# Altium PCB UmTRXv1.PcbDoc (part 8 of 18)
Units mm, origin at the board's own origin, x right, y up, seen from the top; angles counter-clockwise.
Board outline 172 x 113 mm, 6 copper layers (Top Layer, GND, MidLayer1, Mid-Layer 2, InternalPlane2, Bottom Layer); 766 components, 613 nets, 3008 pads, 1360 vias.
Unrouted connection lines stored in the file: 2.
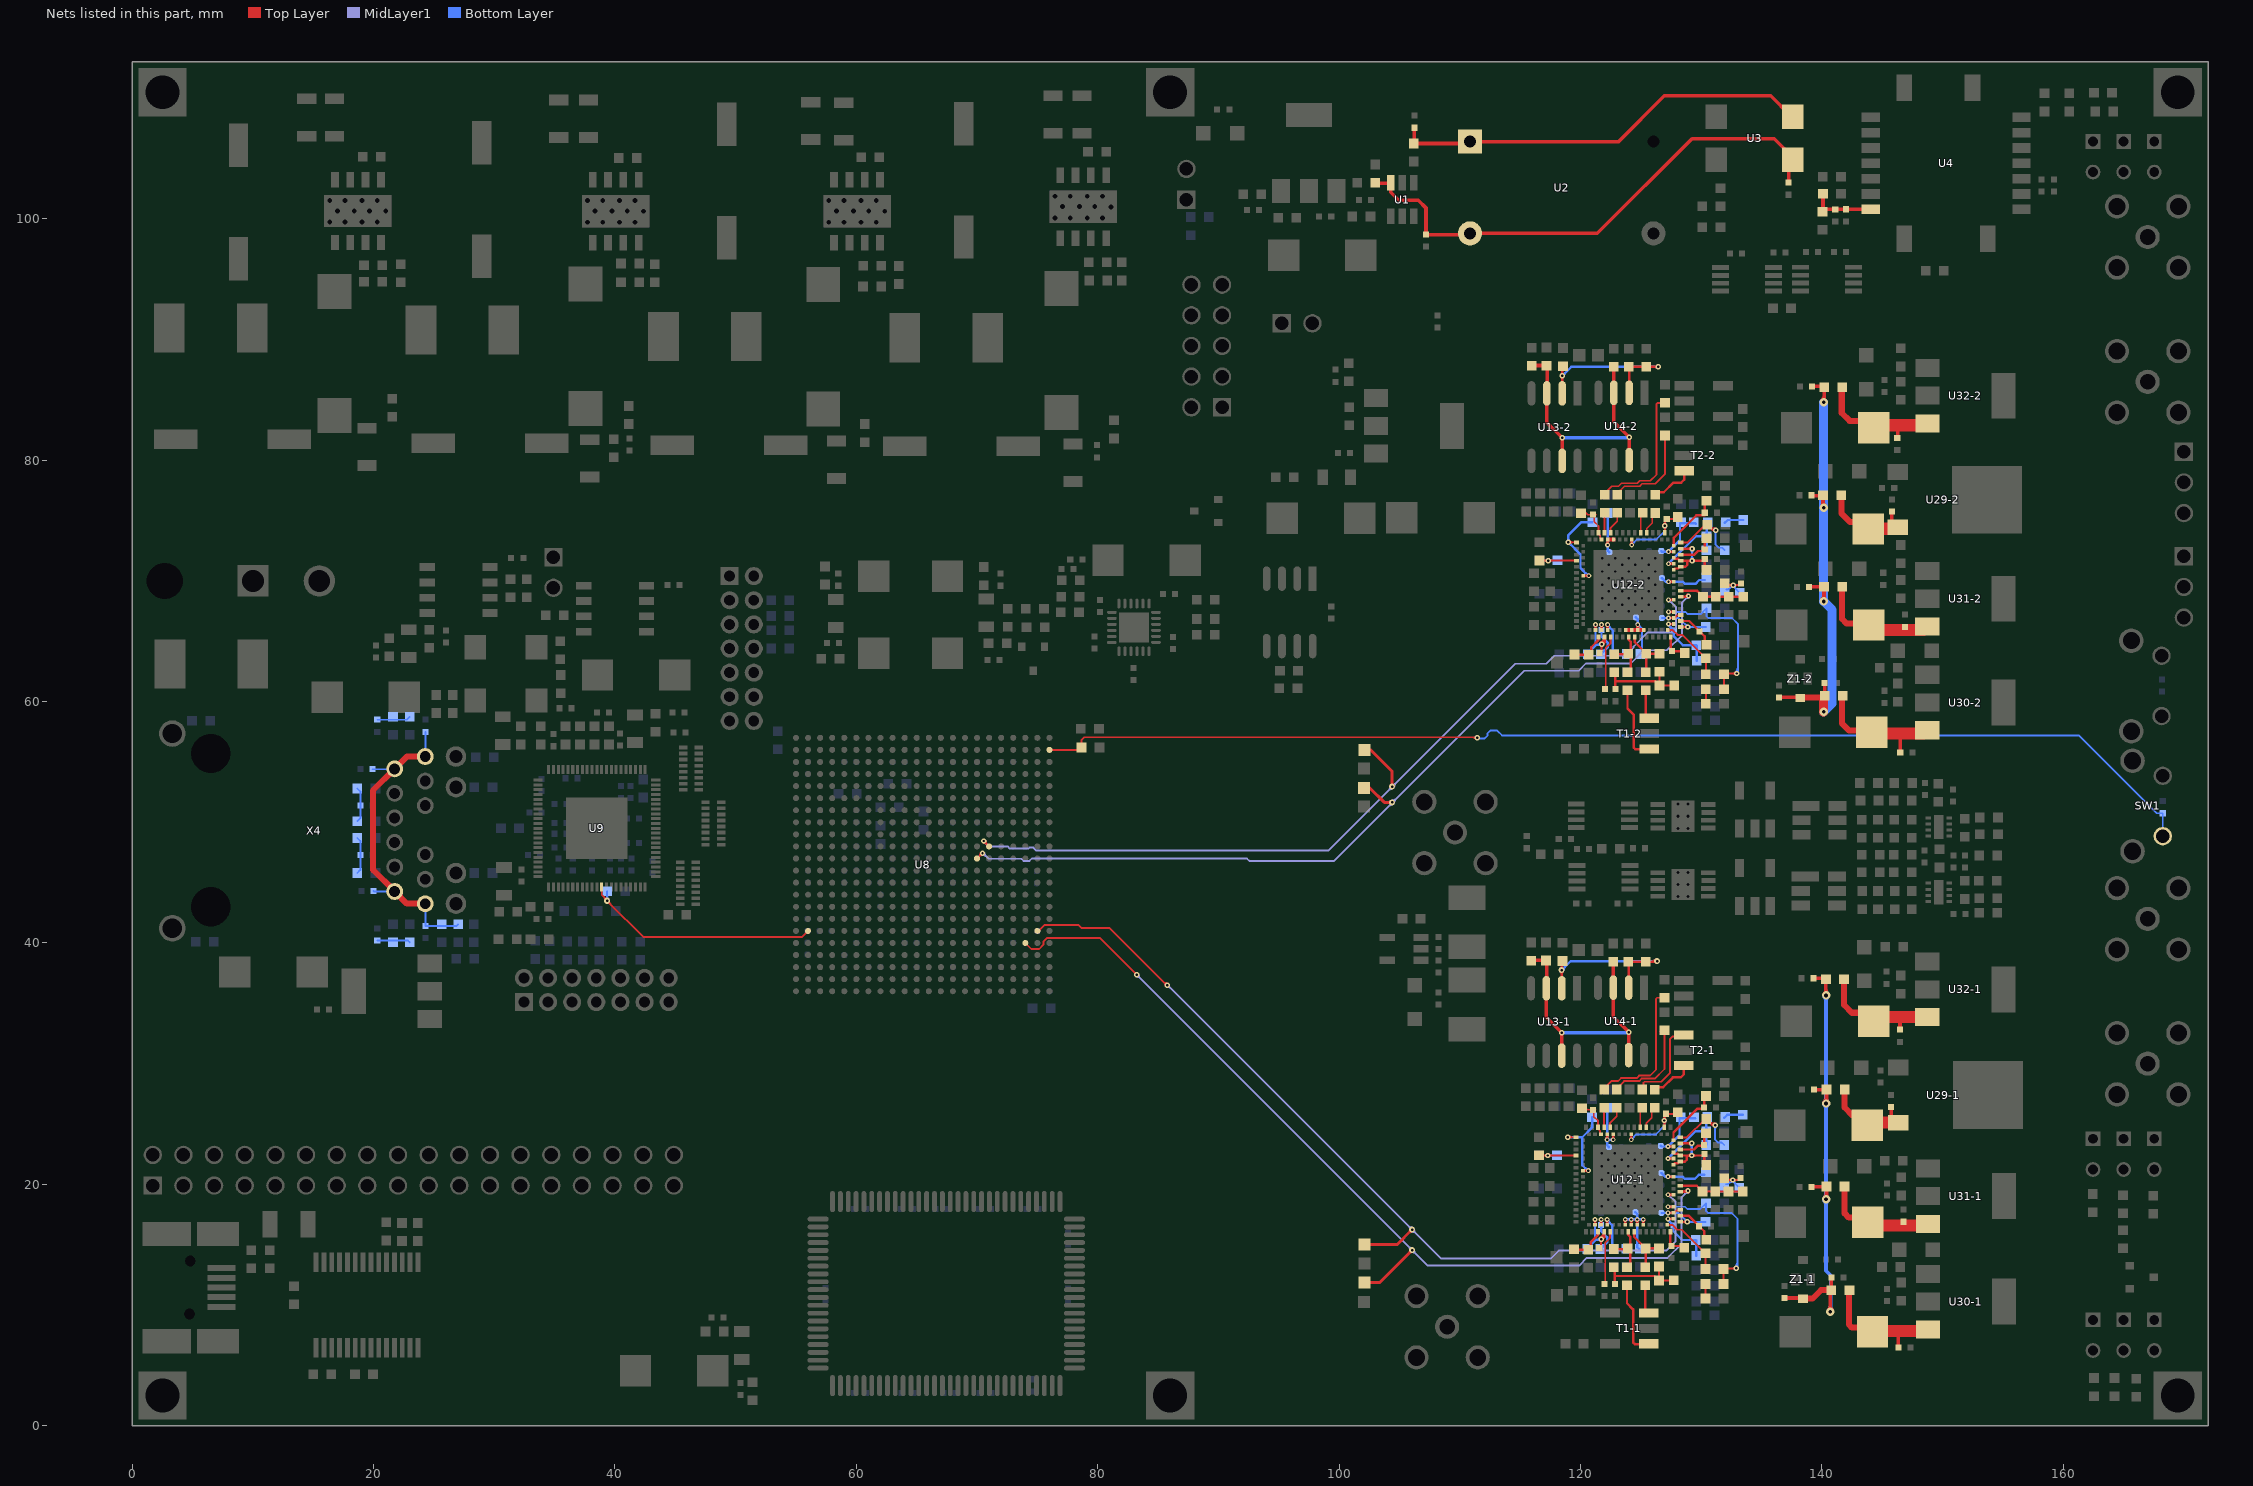
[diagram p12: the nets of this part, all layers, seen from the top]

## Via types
v1: diameter 0.45, hole 0.2, Top Layer to Bottom Layer, tented both sides, 554 vias
v2: diameter 0.5, hole 0.2, Top Layer to Bottom Layer, tented both sides, 468 vias
v3: diameter 0.7, hole 0.3, Top Layer to Bottom Layer, tented both sides, 206 vias
v4: diameter 0.4, hole 0.2, Top Layer to Bottom Layer, tented both sides, 82 vias
v5: diameter 0.8, hole 0.3, Top Layer to Bottom Layer, tented both sides, 16 vias
v6: diameter 0.6, hole 0.25, Top Layer to Bottom Layer, tented both sides, 16 vias
v7: diameter 0.5, hole 0.3, Top Layer to Bottom Layer, tented both sides, 8 vias
v8: diameter 0.7, hole 0.3, Top Layer to Bottom Layer, 4 vias
v9: diameter 0.6, hole 0.3, Top Layer to Bottom Layer, tented both sides, 4 vias
v10: diameter 0.5, hole 0.2, Top Layer to Bottom Layer, 2 vias

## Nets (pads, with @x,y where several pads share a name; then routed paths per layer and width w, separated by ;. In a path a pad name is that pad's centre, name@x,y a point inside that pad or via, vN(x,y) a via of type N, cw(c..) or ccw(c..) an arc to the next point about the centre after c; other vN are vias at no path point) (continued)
MDIO: R92.2 U8.F21 U9.54 | length 22.3
  Top Layer w0.15: U9.54@38.9,44.625 38.9,44 39.55,43.35 v2@39.5,43.35 ; 39.016,43.884 cw(c38.632,43.5) v2@39.175,43.5 ; 39.137,43.763 ccw(c39.35,43.977) v2@39.35,43.675 ; v2@39.35,43.325 cw(c39.35,42.903) 39.649,43.201 cw(c39.947,43.5) v2@39.525,43.5 ; v2@39.45,43.4 v2@39.5,43.35 ; U8.F21@56,41 55.5,40.5 42.35,40.5 v2@39.5,43.35
  Bottom Layer w0.15: v2@39.226,43.624 ccw(c38.928,43.922) 39.35,43.922 ccw(c39.772,43.922) v2@39.474,43.624 ; v2(39.35,43.5) R92.2@39.35,44.287
MISO1: U8.F2 U12-1.68 X21.1 | length 78
  Top Layer w0.15: U8.F2@75,41 75.1,41 75.6,41.5 78.4,41.5 78.65,41.25 80.966,41.25 85.75,36.466 v1@85.75,36.45 ; 85.435,36.78 ccw(c85.75,37.095) v1@85.75,36.65 ; 85.518,36.697 cw(c85.321,36.5) v1@85.6,36.5
  Top Layer w0.2: v4@127.282,19.138 U12-1.68@127.707,19.138 ; v4@127.328,19.067 cw(c127.498,18.897) 127.498,19.138 cw(c127.498,19.379) v4@127.328,19.209
  Top Layer w0.25: X21.1@102.1,15 104.8,15 v2(106.05,16.25) ; v2@105.925,16.25 cw(c105.623,16.25) 105.837,16.037 cw(c106.05,15.823) v2@106.05,16.125
  MidLayer1 w0.15: v1@85.75,36.35 cw(c85.75,35.867) 86.091,36.209 ; v1@85.775,36.525 108.457,13.843 117.543,13.843 118.208,14.508 127.112,14.508 127.882,15.278 127.882,18.543 127.287,19.138 v4(127.257,19.138) ; v1@85.9,36.5 ccw(c86.141,36.5) 85.971,36.329 ; v2@105.875,16.25 ccw(c105.453,16.25) 105.751,16.549 ccw(c106.05,16.847) v2@106.05,16.425 ; v2@106.05,16.075 cw(c106.05,15.653) 106.349,15.951 cw(c106.647,16.25) v2@106.225,16.25 ; v4@127.257,19.013 cw(c127.257,18.638) 127.522,18.903 ; v4@127.382,19.138 ccw(c127.611,19.138) 127.449,18.976
  other v1: 85.75,36.5
MISO2: U8.N6 U12-2.68 X25.1 | length 77.4
  Top Layer w0.15: v1@70.55,48.275 cw(c70.55,47.853) 70.849,48.151 cw(c71.147,48.45) v1@70.725,48.45 ; v1(70.55,48.45) U8.N6@71,48
  Top Layer w0.2: v4@127.321,68.43 U12-2.68@127.746,68.43 ; v4@127.367,68.359 cw(c127.537,68.188) 127.537,68.43 cw(c127.537,68.671) v4@127.367,68.501
  Top Layer w0.25: X25.1@102.1,56 102.6,56 104.4,54.2 v2(104.4,52.95) ; v2@104.312,53.038 ccw(c104.098,53.252) 104.4,53.252 ccw(c104.702,53.252) v2@104.488,53.038
  MidLayer1 w0.15: v1@70.55,48.275 cw(c70.55,47.853) 70.849,48.151 cw(c71.147,48.45) v1@70.725,48.45 ; v1(70.55,48.45) 71,48 72.551,48 72.726,47.825 74.259,47.825 74.334,47.9 74.666,47.9 74.916,47.65 99.1,47.65 v2(104.4,52.95) 114.584,63.134 117.172,63.134 117.836,63.798 119.279,63.798 119.281,63.8 119.819,63.8 119.821,63.798 123.718,63.798 124.4,64.481 124.4,64.569 125.548,65.717 127.467,65.717 127.921,66.171 127.921,67.835 127.326,68.43 v4(127.296,68.43) ; v2@104.225,52.95 cw(c103.803,52.95) 104.101,52.651 cw(c104.4,52.353) v2@104.4,52.775 ; v2@104.4,53.125 ccw(c104.4,53.547) 104.699,53.249 ccw(c104.997,52.95) v2@104.575,52.95 ; v4@127.296,68.305 cw(c127.296,67.93) 127.561,68.195 ; v4@127.421,68.43 ccw(c127.65,68.43) 127.488,68.268
MOSI1: U8.E3 U12-1.69 X20.1 | length 81.5
  Top Layer w0.15: U8.E3@74,40 74.5,39.5 75.15,39.5 75.5,39.85 75.5,40.101 75.824,40.425 80.175,40.425 v1(83.25,37.35) ; v1@83.1,37.35 ccw(c82.738,37.35) 82.994,37.606 ccw(c83.25,37.862) v1@83.25,37.5
  Top Layer w0.2: U12-1.69@128.282,19.388 128.931,19.388 128.961,19.358 128.961,19.408 v1(128.911,19.458) ; U12-1.69@128.44,19.388 ccw(c128.44,19.929) v1@128.823,19.547
  Top Layer w0.25: X20.1@102.1,11.85 103.35,11.85 v2(106.05,14.55) ; v2@105.925,14.55 cw(c105.623,14.55) 105.837,14.337 cw(c106.05,14.123) v2@106.05,14.425
  MidLayer1 w0.15: v1@83.25,37.2 cw(c83.25,36.838) 83.506,37.094 cw(c83.762,37.35) v1@83.4,37.35 ; v1(83.25,37.35) v2(106.05,14.55) 107.332,13.268 119.9,13.268 120.532,13.9 127.211,13.9 128.384,15.074 128.384,18.932 v1(128.911,19.458) ; v2@105.875,14.55 ccw(c105.453,14.55) 105.751,14.849 ccw(c106.05,15.147) v2@106.05,14.725 ; v2@106.05,14.375 cw(c106.05,13.953) 106.349,14.251 cw(c106.647,14.55) v2@106.225,14.55 ; v1@128.761,19.458 cw(c128.399,19.458) 128.655,19.202 cw(c128.911,18.946) v1@128.911,19.308
MOSI2: U8.M7 U12-2.69 X24.1 | length 78
  Top Layer w0.15: U8.M7@70,47 v1(70.45,47.45) ; v1@70.275,47.45 cw(c69.853,47.45) 70.151,47.151 cw(c70.45,46.853) v1@70.45,47.275
  Top Layer w0.2: U12-2.69@128.321,68.68 128.97,68.68 129,68.65 129,68.7 v1(128.95,68.75) ; U12-2.69@128.479,68.68 ccw(c128.479,69.221) v1@128.862,68.838
  Top Layer w0.25: X24.1@102.05,52.85 102.55,52.85 103.75,51.65 v2(104.4,51.65) ; v2@104.312,51.562 ccw(c104.098,51.348) 104.098,51.65 ccw(c104.098,51.952) v2@104.312,51.738
  MidLayer1 w0.15: v1@70.45,47.275 cw(c70.45,46.721) 70.842,47.113 ; v1(70.45,47.45) 70.505,47.45 70.98,46.975 73.671,46.975 73.846,46.8 74.336,46.8 74.536,47 92.364,47 92.564,46.8 99.599,46.8 115.359,62.56 119.853,62.56 120.448,63.155 124.155,63.155 125.25,64.25 127.163,64.25 128.423,65.51 128.423,68.223 v1(128.95,68.75) ; v1@70.625,47.45 ccw(c70.916,47.45) 70.71,47.244 ; 104.067,51.268 ccw(c103.684,51.65) v2@104.225,51.65 ; 104.185,51.386 cw(c104.4,51.171) v2@104.4,51.475 ; v2@104.4,51.825 ccw(c104.4,52.366) 104.782,51.983 ; v2@104.575,51.65 cw(c104.879,51.65) 104.664,51.865 ; v1@128.8,68.75 cw(c128.438,68.75) 128.694,68.494 cw(c128.95,68.238) v1@128.95,68.6
NetC5_2: C5.2 R4.2 U2.1 U3.1 | length 34.8
  Top Layer w0.3: R4.2@106.189,106.25 106.239,106.3 C5.2@106.239,107.55 ; R4.2@106.25,106.25 110.7,106.25 U2.1@110.85,106.4 123.15,106.4 126.95,110.2 135.756,110.2 U3.1@137.4,108.556
NetC8_1: C8.1 C275.2 R2.2 R3.2 U1.3 U2.14 U3.4 | length 44.4
  Top Layer w0.3: R3.2@102.8,102.937 U1.3@104.288,102.937 ; U1.3@104.288,102.985 U1.3@104.288,102.937 ; U1.3@104.303,102.937 U1.3@104.288,102.937 ; C8.1@107.2,98.7 U2.14@110.85,98.7 ; C8.1@107.2,98.708 107.2,100.9 106.55,101.55 104.939,101.55 104.288,102.201 U1.3@104.288,102.937 ; U2.14@110.85,98.8 121.4,98.8 129.25,106.65 136.05,106.65 U3.4@137.7,105 ; C275.2@137.25,103 137.25,104.55 U3.4@137.6,104.9
NetC10_1: C10.1 C11.1 L2.1 R10.2 U4.16 | length 5.5
  Top Layer w0.3: L2.1@140.05,100.6 L2.1@140.093,100.643 ; R10.2@140.093,102.077 L2.1@140.093,100.643 ; U4.16@144.05,100.79 140.24,100.79 L2.1@140.093,100.643
NetC26_1: C26.1 R22.2 SW1.1 U8.AA1 | length 99.1
  Top Layer w0.15: U8.AA1@76,56 78.4,56 R22.2@78.65,56.25 ; R22.2@78.65,56.2 R22.2@78.65,56.25 ; R22.2@78.7,56.3 R22.2@78.65,56.25 ; 110.967,57.05 cw(c110.967,56.517) v1@111.344,56.894 ; 111.209,57.05 ccw(c111.209,57.241) v1@111.344,57.106 ; v1(111.45,57) 111.55,57 111.5,57.05 78.9,57.05 78.65,56.8 R22.2@78.65,56.25
  Bottom Layer w0.15: v1(111.45,57) 111.5,56.95 112.066,56.95 112.3,57.184 112.3,57.366 112.534,57.6 113.1,57.6 113.498,57.202 161.298,57.202 167.75,50.75 C26.1@168.25,50.75 SW1.1@168.25,48.85
NetC28_1: C28.1 C29.1 C30.1 C31.1 C32.2 L4.2 X4.1 X4.6 X4.7 X4.12 | length 27.9
  Top Layer w0.5: X4.7@24.28,43.254 22.756,43.254 X4.1@21.74,44.27 19.95,46.06 19.95,52.64 X4.6@21.74,54.43 22.756,55.446 X4.12@24.28,55.446
  Bottom Layer w0.15: C29.1@19.9,54.4 21.71,54.4 X4.6@21.74,54.43 ; C30.1@20,44.3 20.03,44.27 X4.1@21.74,44.27 ; X4.7@24.28,43.254 24.3,43.234 C31.1@24.3,41.4 26.85,41.4 L4.2@27,41.55 ; X4.12@24.28,55.446 24.3,55.466 C28.1@24.3,57.5
NetC33_1: C33.1 R45.1 R47.1 | length 2.8
  Bottom Layer w0.15: C33.1@20.3,58.5 22.75,58.5 R45.1@23,58.75
NetC34_1: C34.1 R48.1 R49.1 | length 2.9
  Bottom Layer w0.15: R48.1@18.65,50.1 18.9,50.35 C34.1@18.9,51.4 18.9,52.55 R49.1@18.65,52.8
NetC35_1: C35.1 R50.1 R51.1 | length 3.1
  Bottom Layer w0.15: R51.1@18.65,45.8 18.9,46.05 C35.1@18.9,47.3 18.9,48.45 R50.1@18.65,48.7
NetC36_1: C36.1 R58.1 R59.1 | length 2.8
  Bottom Layer w0.15: C36.1@20.3,40.2 22.85,40.2 R58.1@23,40.05
NetC45-1_2: C45-1.2 L6-1.2 R156-1.2 R157-1.1 U12-1.71 | length 5
  Top Layer w0.2: U12-1.71@128.282,19.888 129.631,19.888 R156-1.2@129.819,19.7 ; R156-1.2@130.111,19.408 C45-1.2@131.161,19.408 R157-1.1@132.261,19.408 L6-1.2@133.461,19.408
NetC45-2_2: C45-2.2 L6-2.2 R156-2.2 R157-2.1 U12-2.71 | length 5
  Top Layer w0.2: U12-2.71@128.321,69.18 129.67,69.18 R156-2.2@129.858,68.992 ; R156-2.2@130.15,68.7 C45-2.2@131.2,68.7 R157-2.1@132.3,68.7 L6-2.2@133.5,68.7
NetC46-1_1: C46-1.1 C47-1.1 C48-1.1 C49-1.1 C50-1.1 L7-1.1 L8-1.1 L9-1.1 L10-1.1 Z1-1.3 | length 48.3
  Top Layer w0.3: C46-1.1@136.89,10.581 138.39,10.581 Z1-1.3@138.44,10.531 ; C49-1.1@139.144,19.795 140.34,19.795 140.363,19.795 L9-1.1@140.384,19.816 140.384,18.784 v3(140.35,18.75) ; C50-1.1@139.311,37.076 140.27,37.076 L10-1.1@140.34,37.006 140.34,35.61 140.35,35.6 v3(140.35,35.65) ; C47-1.1@139.346,27.853 140.38,27.853 L7-1.1@140.39,27.863 140.39,26.74 v3(140.35,26.7) ; v3@140.209,18.891 ccw(c139.784,19.316) 140.384,19.316 ; v3@140.209,26.841 ccw(c139.77,27.28) 140.39,27.28 ; v3@140.209,35.791 ccw(c139.891,36.109) 140.34,36.109 ; 140.34,36.157 ccw(c140.857,36.157) v3@140.491,35.791 ; 140.384,19.15 ccw(c140.75,19.15) v3@140.491,18.891 ; 140.39,27.086 ccw(c140.736,27.086) v3@140.491,26.841 ; v3@140.559,9.591 ccw(c140.217,9.933) 140.7,9.933 ccw(c141.183,9.933) v3@140.841,9.591 ; v3(140.7,9.45) 140.7,11.141 L8-1.1@140.79,11.231 C48-1.1@140.79,12.281
  Top Layer w0.5: Z1-1.3@138.44,10.531 139.231,10.531 139.931,11.231 L8-1.1@140.79,11.231 ; L9-1.1@140.34,19.795 140.34,19.861 L9-1.1@140.384,19.816
  Bottom Layer w0.3: v3@140.209,18.609 cw(c139.867,18.267) 140.35,18.267 cw(c140.833,18.267) v3@140.491,18.609 ; v3@140.209,18.891 ccw(c139.867,19.233) 140.35,19.233 ccw(c140.833,19.233) v3@140.491,18.891 ; v3@140.209,26.559 cw(c139.867,26.217) 140.35,26.217 cw(c140.833,26.217) v3@140.491,26.559 ; v3@140.209,26.841 ccw(c139.867,27.183) 140.35,27.183 ccw(c140.833,27.183) v3@140.491,26.841 ; v3@140.209,35.509 cw(c139.867,35.167) 140.35,35.167 cw(c140.833,35.167) v3@140.491,35.509 ; v3(140.35,35.65) v3(140.35,26.7) v3(140.35,18.75) 140.35,12.85 140.75,12.45 140.75,9.5 v3(140.7,9.45) ; v3@140.559,9.591 ccw(c140.096,10.054) 140.75,10.054 ; 140.75,9.812 ccw(c141.062,9.812) v3@140.841,9.591
NetC46-2_1: C46-2.1 C47-2.1 C48-2.1 C49-2.1 C50-2.1 L7-2.1 L8-2.1 L9-2.1 L10-2.1 Z1-2.3 | length 41.4
  Top Layer w0.3: C46-2.1@136.49,60.376 137.99,60.376 Z1-2.3@138.04,60.326 ; C49-2.1@138.988,69.516 L9-2.1@140.184,69.516 140.184,68.334 v3(140.15,68.3) ; C47-2.1@139.096,77.066 L7-2.1@140.1,77.066 ; C50-2.1@139.121,86.12 140.08,86.12 L10-2.1@140.15,86.05 ; v3@140.009,68.441 ccw(c139.584,68.866) 140.184,68.866 ; v3@140.009,76.191 ccw(c139.788,76.412) 140.1,76.412 ; v3@140.009,84.941 ccw(c139.546,85.404) 140.2,85.404 ; 140.1,76.654 ccw(c140.754,76.654) v3@140.291,76.191 ; L7-2.1@140.1,77.1 L7-2.1@140.1,77.066 ; L7-2.1@140.14,77.076 140.13,77.066 L7-2.1@140.1,77.066 ; L8-2.1@140.15,60.386 L8-2.1@140.24,60.476 C48-2.1@140.24,61.526 ; v3(140.15,76.05) 140.1,76.1 L7-2.1@140.1,77.066 ; v3(140.15,84.8) 140.2,84.85 L10-2.1@140.2,86.05 ; 140.184,68.7 ccw(c140.55,68.7) v3@140.291,68.441 ; 140.2,85.162 ccw(c140.512,85.162) v3@140.291,84.941
  Top Layer w0.5: Z1-2.3@138.04,60.326 L8-2.1@140.04,60.326
  Top Layer w0.75: v3(140.15,59.15) L8-2.1@140.15,60.386
  Bottom Layer w0.75: v3(140.15,59.15) 140.85,59.85 140.85,67.6 v3(140.15,68.3) v3(140.15,76.05) v3(140.15,84.8)
NetC51-1_1: C51-1.1 C55-1.1 L7-1.2 U29-1.3 | length 7.9
  Top Layer w0.3: U29-1.3@145.75,25.245 C55-1.1@145.75,26.4 ; U29-1.3@146.512,25.113 U29-1.3@146.644,25.245
  Top Layer w0.5: L7-1.2@141.89,27.863 141.89,26.368 142.57,25.687 C51-1.1@144.52,25.687
  Top Layer w1: C51-1.1@144.44,24.813 144.74,25.113 U29-1.3@146.512,25.113
NetC51-2_1: C51-2.1 C55-2.1 L7-2.2 U29-2.3 | length 7.8
  Top Layer w0.3: U29-2.3@145.8,74.75 C55-2.1@145.8,75.75 C55-2.1@145.8,75.803 ; U29-2.3@146.262,74.326 U29-2.3@146.394,74.458
  Top Layer w0.5: L7-2.2@141.64,77.076 141.64,75.581 142.32,74.9 C51-2.1@144.27,74.9
  Top Layer w1: C51-2.1@144.19,74.026 144.49,74.326 U29-2.3@146.262,74.326
NetC52-1_1: C52-1.1 C56-1.1 L8-1.2 U30-1.3 | length 10.9
  Top Layer w0.3: C56-1.1@146.348,6.489 146.348,7.791 ; 146.802,7.909 146.865,7.846
  Top Layer w0.5: L8-1.2@142.25,11.131 142.25,8.368 142.491,8.127 143.222,8.127 C52-1.1@144.196,7.153
  Top Layer w1: C52-1.1@144.505,7.846 146.865,7.846 148.655,7.846 U30-1.3@148.79,7.981
NetC52-2_1: C52-2.1 C56-2.1 L8-2.2 U30-2.3 | length 10.9
  Top Layer w0.3: C56-2.1@146.498,55.794 146.498,57.096 ; 146.552,57.404 146.615,57.341
  Top Layer w0.5: L8-2.2@141.69,60.476 141.69,58.173 142.241,57.623 142.972,57.623 C52-2.1@143.946,56.648
  Top Layer w1: C52-2.1@144.255,57.341 146.615,57.341 148.405,57.341 U30-2.3@148.54,57.476
NetC53-1_1: C53-1.1 C57-1.1 L9-1.2 U31-1.3 | length 8.9
  Top Layer w0.3: 146.729,16.524 146.794,16.589
  Top Layer w0.5: L9-1.2@141.884,19.816 141.884,17.594 142.239,17.239 C53-1.1@143.578,17.239 ; C53-1.1@143.628,16.589 C53-1.1@144.34,15.877
  Top Layer w1: C53-1.1@145.083,16.589 146.794,16.589 148.652,16.589 U31-1.3@148.79,16.727
NetC53-2_1: C53-2.1 C57-2.1 L9-2.2 U31-2.3 | length 8.4
  Top Layer w0.3: 146.479,65.874 146.544,65.939
  Top Layer w0.5: L9-2.2@141.684,69.516 141.684,66.843 142.039,66.489 C53-2.1@143.378,66.489
  Top Layer w1: C53-2.1@144.833,65.939 146.544,65.939 148.402,65.939 U31-2.3@148.54,66.076
NetC54-1_1: C54-1.1 C58-1.1 L10-1.2 U32-1.3 | length 10.6
  Top Layer w0.3: C58-1.1@146.477,32.811 146.477,33.856
  Top Layer w0.5: L10-1.2@141.84,37.006 141.84,34.869 142.492,34.217 C54-1.1@144.225,34.217
  Top Layer w1: C54-1.1@144.29,33.506 144.29,33.856 146.477,33.856 U32-1.3@148.74,33.856
NetC54-2_1: C54-2.1 C58-2.1 L10-2.2 U32-2.3 | length 10.6
  Top Layer w0.3: C58-2.1@146.287,81.855 146.287,82.9
  Top Layer w0.5: L10-2.2@141.65,86.05 141.65,83.913 142.302,83.261 C54-2.1@144.035,83.261
  Top Layer w1: C54-2.1@144.1,82.55 144.1,82.9 146.287,82.9 U32-2.3@148.55,82.9
NetC59-1_2: C59-1.2 L19-1.1 U12-1.61 | length 3.1
  Top Layer w0.2: U12-1.61@128.282,17.388 128.981,17.388 130.257,16.112 130.257,15.738 L19-1.1@130.407,15.588
NetC59-2_2: C59-2.2 L19-2.1 U12-2.61 | length 3.1
  Top Layer w0.2: U12-2.61@128.321,66.68 129.02,66.68 130.296,65.404 130.296,65.03 L19-2.1@130.446,64.88
NetC60-1_2: C60-1.2 L18-1.1 R104-1.1 R105-1.1 | length 5.1
  Top Layer w0.15: R105-1.1@131.962,20.358 v1(132.611,20.358) C60-1.2@133.211,20.358 ; v1@132.505,20.252 ccw(c132.249,19.996) 132.249,20.358 ccw(c132.249,20.72) v1@132.505,20.464 ; v1@132.717,20.252 cw(c132.973,19.996) 132.973,20.358 cw(c132.973,20.72) v1@132.717,20.464 ; C60-1.2@133.211,20.558 C60-1.2@133.261,20.508
  Bottom Layer w0.15: R104-1.1@132.061,20.008 132.211,20.008 132.561,20.358 v1(132.611,20.358) 132.611,20.258 L18-1.1@133.161,19.708 ; R104-1.1@132.27,20.067 cw(c132.611,19.725) v1@132.611,20.208 ; 132.39,20.188 ccw(c132.22,20.358) v1@132.461,20.358 ; v1@132.761,20.358 ccw(c133.365,20.358) L18-1.1@132.938,19.931
NetC60-2_2: C60-2.2 L18-2.1 R104-2.1 R105-2.1 | length 5.1
  Top Layer w0.15: R105-2.1@132.001,69.65 v1(132.65,69.65) C60-2.2@133.25,69.65 ; v1@132.544,69.544 ccw(c132.288,69.288) 132.288,69.65 ccw(c132.288,70.012) v1@132.544,69.756 ; v1@132.756,69.544 cw(c133.012,69.288) 133.012,69.65 cw(c133.012,70.012) v1@132.756,69.756 ; C60-2.2@133.25,69.85 C60-2.2@133.3,69.8
  Bottom Layer w0.15: R104-2.1@132.1,69.3 132.25,69.3 132.6,69.65 v1(132.65,69.65) 132.65,69.55 L18-2.1@133.2,69 ; R104-2.1@132.309,69.359 cw(c132.65,69.017) v1@132.65,69.5 ; 132.429,69.479 ccw(c132.259,69.65) v1@132.5,69.65 ; v1@132.8,69.65 ccw(c133.404,69.65) L18-2.1@132.977,69.223
NetC61-1_2: C61-1.2 L16-1.1 U12-1.83 | length 3.2
  Top Layer w0.2: U12-1.83@128.282,22.888 129.407,22.888 129.707,23.188 130.257,23.188 130.257,24.038 L16-1.1@130.407,24.188
NetC61-2_2: C61-2.2 L16-2.1 U12-2.83 | length 3.2
  Top Layer w0.2: U12-2.83@128.321,72.18 129.446,72.18 129.746,72.48 130.296,72.48 130.296,73.33 L16-2.1@130.446,73.48
NetC62-1_2: C62-1.2 L11-1.1 U12-1.35 | length 3.3
  Top Layer w0.2: v4@121.636,17.017 cw(c121.466,16.847) 121.707,16.847 cw(c121.948,16.847) v4@121.778,17.017 ; U12-1.35@121.707,16.638 v4@121.707,17.063
  Bottom Layer w0.2: L11-1.1@121.657,14.638 122.211,15.192 122.211,15.608 121.707,16.112 C62-1.2@121.707,16.638 ; v4@121.657,17.038 v4(121.707,17.088)
NetC62-2_2: C62-2.2 L11-2.1 U12-2.35 | length 3.3
  Top Layer w0.2: v4@121.675,66.309 cw(c121.505,66.138) 121.746,66.138 cw(c121.987,66.138) v4@121.817,66.309 ; U12-2.35@121.746,65.93 v4@121.746,66.355
  Bottom Layer w0.2: L11-2.1@121.696,63.93 122.25,64.484 122.25,64.9 121.746,65.404 C62-2.2@121.746,65.93 ; v4@121.696,66.33 v4(121.746,66.38)
NetC63-1_2: C63-1.2 L20-1.1 U12-1.33 U12-1.36 | length 8.4
  Top Layer w0.15: C63-1.2@121.557,14.738 121.711,14.892 v1(121.711,15.458) ; v1@121.605,15.352 cw(c121.349,15.096) 121.711,15.096 cw(c122.073,15.096) v1@121.817,15.352
  Top Layer w0.2: v4@121.136,17.017 cw(c120.966,16.847) 121.207,16.847 cw(c121.448,16.847) v4@121.278,17.017 ; U12-1.33@121.207,16.638 v4@121.207,17.063 ; v1@121.654,15.57 ccw(c121.403,16.063) U12-1.36@121.957,16.063 121.957,15.604 ; v1(121.711,15.458) 121.761,15.408 121.957,15.604 ; v1@121.745,15.391 ccw(c121.569,15.737) 121.957,15.737 ; v1@121.765,15.571 ccw(c121.837,15.724) 121.957,15.604
  Bottom Layer w0.15: v4@121.119,17 cw(c120.895,16.777) 121.211,16.777 ; v4(121.207,17.088) 121.211,17.084 121.211,15.408 ; 121.211,16.796 cw(c121.499,16.796) v4@121.295,17
  Bottom Layer w0.2: L20-1.1@120.557,14.638 120.557,14.704 121.211,15.358 121.211,15.408 121.761,15.408 v1(121.711,15.458) ; 121.289,15.408 ccw(c121.289,15.88) v1@121.623,15.547
NetC63-2_2: C63-2.2 L20-2.1 U12-2.33 U12-2.36 | length 8.4
  Top Layer w0.15: C63-2.2@121.596,64.03 121.75,64.184 v1(121.75,64.75) ; v1@121.644,64.644 cw(c121.388,64.388) 121.75,64.388 cw(c122.112,64.388) v1@121.856,64.644
  Top Layer w0.2: v4@121.175,66.309 cw(c121.005,66.138) 121.246,66.138 cw(c121.487,66.138) v4@121.317,66.309 ; U12-2.33@121.246,65.93 v4@121.246,66.355 ; v1@121.693,64.861 ccw(c121.442,65.355) U12-2.36@121.996,65.355 121.996,64.896 ; v1(121.75,64.75) 121.8,64.7 121.996,64.896 ; v1@121.784,64.683 ccw(c121.608,65.029) 121.996,65.029 ; v1@121.804,64.863 ccw(c121.876,65.016) 121.996,64.896
  Bottom Layer w0.15: v4@121.158,66.291 cw(c120.934,66.068) 121.25,66.068 ; v4(121.246,66.38) 121.25,66.376 121.25,64.7 ; 121.25,66.088 cw(c121.538,66.088) v4@121.334,66.291
  Bottom Layer w0.2: L20-2.1@120.596,63.93 120.596,63.996 121.25,64.65 121.25,64.7 121.8,64.7 v1(121.75,64.75) ; 121.328,64.7 ccw(c121.328,65.172) v1@121.662,64.838
NetC73-1_1: C73-1.1 C78-1.1 L14-1.2 U12-1.60 | length 5.9
  Top Layer w0.2: v4@127.282,17.138 U12-1.60@127.707,17.138 ; v4@127.328,17.067 cw(c127.498,16.897) 127.498,17.138 cw(c127.498,17.379) v4@127.328,17.209
  Bottom Layer w0.2: v4(127.257,17.138) 127.257,17.038 C78-1.1@127.707,16.588 127.707,16.112 128.431,15.388 C73-1.1@129.557,15.388 129.607,15.338 L14-1.2@129.607,14.088 ; v4@127.357,17.138 ccw(c127.84,17.138) C78-1.1@127.498,16.797
NetC73-2_1: C73-2.1 C78-2.1 L14-2.2 U12-2.60 | length 5.9
  Top Layer w0.2: v4@127.321,66.43 U12-2.60@127.746,66.43 ; v4@127.367,66.359 cw(c127.537,66.188) 127.537,66.43 cw(c127.537,66.671) v4@127.367,66.501
  Bottom Layer w0.2: v4(127.296,66.43) 127.296,66.33 C78-2.1@127.746,65.88 127.746,65.404 128.47,64.68 C73-2.1@129.596,64.68 129.646,64.63 L14-2.2@129.646,63.38 ; v4@127.396,66.43 ccw(c127.879,66.43) C78-2.1@127.537,66.088
NetC74-1_1: C74-1.1 L12-1.2 U12-1.37 | length 4.8
  Top Layer w0.2: v4@122.136,17.017 cw(c121.966,16.847) 122.207,16.847 cw(c122.448,16.847) v4@122.278,17.017 ; U12-1.37@122.207,16.638 v4@122.207,17.063
  Bottom Layer w0.2: v4(122.207,17.088) 122.207,17.022 122.636,16.593 122.636,14.759 C74-1.1@122.757,14.638 L12-1.2@123.757,14.638 ; v4@122.307,17.088 ccw(c122.707,17.088) 122.424,16.805
NetC74-2_1: C74-2.1 L12-2.2 U12-2.37 | length 4.8
  Top Layer w0.2: v4@122.175,66.309 cw(c122.005,66.138) 122.246,66.138 cw(c122.487,66.138) v4@122.317,66.309 ; U12-2.37@122.246,65.93 v4@122.246,66.355
  Bottom Layer w0.2: v4(122.246,66.38) 122.246,66.314 122.675,65.885 122.675,64.051 C74-2.1@122.796,63.93 L12-2.2@123.796,63.93 ; v4@122.346,66.38 ccw(c122.746,66.38) 122.463,66.097
NetC75-1_1: C75-1.1 C79-1.1 L15-1.2 U12-1.84 | length 6.2
  Top Layer w0.2: v4@127.282,23.138 U12-1.84@127.707,23.138 ; v4@127.328,23.067 cw(c127.498,22.897) 127.498,23.138 cw(c127.498,23.379) v4@127.328,23.209
  Bottom Layer w0.2: C79-1.1@126.657,23.188 126.707,23.138 v4(127.257,23.138) 128.207,24.088 128.207,25.488 129.411,25.488 129.481,25.488 L15-1.2@129.511,25.458 ; v4@127.186,23.067 ccw(c127.016,22.897) 127.016,23.138 ccw(c127.016,23.379) v4@127.186,23.209 ; v4@127.257,23.238 ccw(c127.257,23.479) 127.428,23.309 ccw(c127.598,23.138) v4@127.357,23.138
NetC75-2_1: C75-2.1 C79-2.1 L15-2.2 U12-2.84 | length 6.2
  Top Layer w0.2: v4@127.321,72.43 U12-2.84@127.746,72.43 ; v4@127.367,72.359 cw(c127.537,72.188) 127.537,72.43 cw(c127.537,72.671) v4@127.367,72.501
  Bottom Layer w0.2: C79-2.1@126.696,72.48 126.746,72.43 v4(127.296,72.43) 128.246,73.38 128.246,74.78 129.45,74.78 129.52,74.78 L15-2.2@129.55,74.75 ; v4@127.225,72.359 ccw(c127.055,72.188) 127.055,72.43 ccw(c127.055,72.671) v4@127.225,72.501 ; v4@127.296,72.53 ccw(c127.296,72.771) 127.467,72.601 ccw(c127.637,72.43) v4@127.396,72.43
NetC76-1_1: C76-1.1 L17-1.2 U12-1.7 | length 5.6
  Top Layer w0.15: C76-1.1@116.562,22.405 116.579,22.388 v1(117.295,22.388) ; v1@117.189,22.282 ccw(c116.933,22.026) 116.933,22.388 ccw(c116.933,22.75) v1@117.189,22.494 ; v1(117.295,22.388) U12-1.7@119.632,22.388 ; v1@117.401,22.282 cw(c117.658,22.025) 117.658,22.388 ; v1@117.401,22.494 ccw(c117.657,22.749) 117.657,22.388
  Bottom Layer w0.15: v1(117.295,22.388) 118.041,22.388 L17-1.2@118.061,22.408 ; v1@117.401,22.282 cw(c117.657,22.026) 117.657,22.388 cw(c117.657,22.75) v1@117.401,22.494
NetC76-2_1: C76-2.1 L17-2.2 U12-2.7 | length 5.6
  Top Layer w0.15: C76-2.1@116.601,71.697 116.618,71.679 v1(117.334,71.679) U12-2.7@119.671,71.68 ; v1@117.228,71.573 ccw(c116.972,71.317) 116.972,71.679 ccw(c116.972,72.042) v1@117.228,71.786 ; v1@117.44,71.573 cw(c117.697,71.316) 117.697,71.68 ; v1@117.44,71.786 ccw(c117.695,72.041) 117.695,71.68
  Bottom Layer w0.15: v1(117.334,71.679) 118.079,71.679 L17-2.2@118.1,71.7 ; v1@117.44,71.573 cw(c117.696,71.317) 117.696,71.679 cw(c117.696,72.042) v1@117.44,71.786
NetC77-1_1: C77-1.1 R103-1.2 U12-1.34 | length 2.9
  Top Layer w0.2: R103-1.2@119.607,14.588 C77-1.1@120.657,14.588 120.791,14.588 120.861,14.658 120.861,15.209 121.457,15.805 U12-1.34@121.457,16.063
NetC77-2_1: C77-2.1 R103-2.2 U12-2.34 | length 2.9
  Top Layer w0.2: R103-2.2@119.646,63.88 C77-2.1@120.696,63.88 120.83,63.88 120.9,63.95 120.9,64.501 121.496,65.097 U12-2.34@121.496,65.355
NetC80-1_1: C80-1.1 L13-1.2 U12-1.74 | length 5.4
  Top Layer w0.2: v4@127.282,20.638 U12-1.74@127.707,20.638 ; v4@127.328,20.567 cw(c127.498,20.397) 127.498,20.638 cw(c127.498,20.879) v4@127.328,20.709
  Bottom Layer w0.2: C80-1.1@126.707,20.938 127.007,20.638 v4(127.257,20.638) 128.457,20.638 128.632,20.463 129.482,20.463 129.807,20.788 L13-1.2@130.257,20.788 ; v4@127.186,20.567 ccw(c127.016,20.397) 127.016,20.638 ccw(c127.016,20.879) v4@127.186,20.709 ; v4@127.328,20.567 cw(c127.498,20.397) 127.498,20.638 cw(c127.498,20.879) v4@127.328,20.709
NetC80-2_1: C80-2.1 L13-2.2 U12-2.74 | length 5.4
  Top Layer w0.2: v4@127.321,69.93 U12-2.74@127.746,69.93 ; v4@127.367,69.859 cw(c127.537,69.688) 127.537,69.93 cw(c127.537,70.171) v4@127.367,70.001
  Bottom Layer w0.2: C80-2.1@126.746,70.23 127.046,69.93 v4(127.296,69.93) 128.496,69.93 128.671,69.755 129.521,69.755 129.846,70.08 L13-2.2@130.296,70.08 ; v4@127.225,69.859 ccw(c127.055,69.688) 127.055,69.93 ccw(c127.055,70.171) v4@127.225,70.001 ; v4@127.367,69.859 cw(c127.537,69.688) 127.537,69.93 cw(c127.537,70.171) v4@127.367,70.001
NetC81-1_1: C81-1.1 U12-1.1 U12-1.12 | length 9
  Top Layer w0.15: v1(118.961,23.908) 119.612,23.908 U12-1.1@119.632,23.888 ; v1@119.067,23.802 cw(c119.323,23.546) 119.323,23.908 cw(c119.323,24.27) v1@119.067,24.014
  Top Layer w0.2: U12-1.12@120.207,21.138 v4@120.632,21.138 ; v4@120.586,21.067 ccw(c120.416,20.897) 120.416,21.138 ccw(c120.416,21.379) v4@120.586,21.209
  Bottom Layer w0.2: v1(118.961,23.908) 118.969,23.9 120.15,23.9 ; v1@119.049,23.82 cw(c119.243,23.626) 119.243,23.9 ; v1@119.049,23.997 ccw(c119.283,24.23) 119.283,23.9 ; 120.374,21.355 ccw(c120.657,21.638) v4@120.657,21.238 ; v4(120.657,21.138) 120.591,21.138 120.15,21.579 120.15,23.9 ; C81-1.1@120.961,25.558 120.961,24.711 120.15,23.9
NetC81-2_1: C81-2.1 U12-2.1 U12-2.12 | length 9.9
  Top Layer w0.15: v1(119,73.2) 119.651,73.2 U12-2.1@119.671,73.18 ; v1@119.106,73.094 cw(c119.362,72.838) 119.362,73.2 cw(c119.362,73.562) v1@119.106,73.306
  Top Layer w0.2: U12-2.12@120.246,70.43 v4@120.671,70.43 ; v4@120.625,70.359 ccw(c120.455,70.188) 120.455,70.43 ccw(c120.455,70.671) v4@120.625,70.501
  Bottom Layer w0.2: v1@118.912,73.288 ccw(c118.698,73.502) 119,73.502 ccw(c119.302,73.502) v1@119.088,73.288 ; v1@119,73.075 cw(c119,72.773) 119.213,72.987 cw(c119.427,73.2) v1@119.125,73.2 ; 120.413,70.647 ccw(c120.696,70.93) v4@120.696,70.53 ; v4(120.696,70.43) 120.63,70.43 120,71.06 120,72.2 v1(119,73.2) 119,73.8 120.05,74.85 C81-2.1@121,74.85
NetC82-1_1: C82-1.1 C83-1.1 R109-1.1 U12-1.64 | length 16.1
  Top Layer w0.15: C83-1.1@131.857,11.738 R109-1.1@131.857,12.988 131.907,13.038 v1(132.907,13.038) ; v1@132.801,12.932 ccw(c132.545,12.676) 132.545,13.038 ccw(c132.545,13.4) v1@132.801,13.144
  Top Layer w0.2: v4@127.282,18.138 U12-1.64@127.707,18.138 ; v4@127.328,18.067 cw(c127.498,17.897) 127.498,18.138 cw(c127.498,18.379) v4@127.328,18.209
  Bottom Layer w0.15: v4(127.257,18.138) 128.666,18.138 128.845,17.958 129.927,17.958 C82-1.1@130.407,18.438 130.407,17.788 130.557,17.638 132.517,17.638 133.011,17.144 133.011,13.142 v1(132.907,13.038) ccw(c132.656,13.289) 133.011,13.289 ; v4@127.345,18.05 cw(c127.559,17.836) 127.559,18.138 cw(c127.559,18.44) v4@127.345,18.226 ; v1@132.801,13.144 ccw(c132.294,13.651) 133.011,13.651
NetC82-2_1: C82-2.1 C83-2.1 R109-2.1 U12-2.64 | length 16.1
  Top Layer w0.15: C83-2.1@131.896,61.03 R109-2.1@131.896,62.28 131.946,62.33 v1(132.946,62.33) ; v1@132.84,62.224 ccw(c132.584,61.968) 132.584,62.33 ccw(c132.584,62.692) v1@132.84,62.436
  Top Layer w0.2: v4@127.321,67.43 U12-2.64@127.746,67.43 ; v4@127.367,67.359 cw(c127.537,67.188) 127.537,67.43 cw(c127.537,67.671) v4@127.367,67.501
  Bottom Layer w0.15: v4(127.296,67.43) 128.704,67.43 128.884,67.25 129.966,67.25 C82-2.1@130.446,67.73 130.446,67.08 130.596,66.93 132.556,66.93 133.05,66.436 133.05,62.434 v1(132.946,62.33) ccw(c132.695,62.581) 133.05,62.581 ; v4@127.384,67.341 cw(c127.598,67.128) 127.598,67.43 cw(c127.598,67.732) v4@127.384,67.518 ; v1@132.84,62.436 ccw(c132.333,62.943) 133.05,62.943
NetC83-1_2: C83-1.2 R106-1.2 | length 1.2
  Top Layer w0.15: R106-1.2@130.357,10.538 C83-1.2@130.357,11.738
NetC83-2_2: C83-2.2 R106-2.2 | length 1.2
  Top Layer w0.15: R106-2.2@130.396,59.83 C83-2.2@130.396,61.03
NetC84-1_2: C84-1.2 R109-1.2 U12-1.57 | length 5.4
  Top Layer w0.15: U12-1.57@127.207,16.638 127.607,16.638 128.007,16.238 128.407,16.238 C84-1.2@130.357,14.288 R109-1.2@130.357,12.988
NetC84-2_2: C84-2.2 R109-2.2 U12-2.57 | length 5.4
  Top Layer w0.15: U12-2.57@127.246,65.93 127.646,65.93 128.046,65.53 128.446,65.53 C84-2.2@130.396,63.58 R109-2.2@130.396,62.28
NetC85-1_2: C85-1.2 U12-1.38 | length 4.5
  Top Layer w0.15: C85-1.2@122.007,11.738 122.061,11.792 122.061,15.158 122.457,15.554 U12-1.38@122.457,16.063
NetC85-2_2: C85-2.2 U12-2.38 | length 4.5
  Top Layer w0.15: C85-2.2@122.046,61.03 122.1,61.084 122.1,64.45 122.496,64.846 U12-2.38@122.496,65.355
NetC86-1_1: C86-1.1 L21-1.1 U12-1.111 U12-1.112 | length 3.2
  Top Layer w0.15: L21-1.1@120.357,26.388 120.557,26.188 C86-1.1@121.107,26.188 ; C86-1.1@121.257,26.188 C86-1.1@121.107,26.188 ; U12-1.111@121.657,24.188 121.607,24.238 121.607,24.438 121.457,24.588 U12-1.112@121.457,24.713 121.457,25.262 121.107,25.612 C86-1.1@121.107,26.188
NetC86-2_1: C86-2.1 L21-2.1 U12-2.111 U12-2.112 | length 3.2
  Top Layer w0.15: L21-2.1@120.396,75.68 120.596,75.48 C86-2.1@121.146,75.48 ; 121.296,75.48 C86-2.1@121.146,75.48 ; U12-2.111@121.696,73.48 121.646,73.53 121.646,73.73 121.496,73.88 U12-2.112@121.496,74.005 121.496,74.554 121.146,74.904 C86-2.1@121.146,75.48
NetC87-1_1: C87-1.1 L22-1.2 U12-1.58 | length 2.3
  Top Layer w0.2: U12-1.58@127.457,16.063 127.457,14.988 C87-1.1@127.557,14.888 128.457,14.888 L22-1.2@128.607,14.738
NetC87-2_1: C87-2.1 L22-2.2 U12-2.58 | length 2.3
  Top Layer w0.2: U12-2.58@127.496,65.355 127.496,64.28 C87-2.1@127.596,64.18 128.496,64.18 L22-2.2@128.646,64.03
NetC88-1_1: C88-1.1 L23-1.1 U12-1.107 U12-1.109 | length 6.7
  Top Layer w0.2: v4@122.136,23.759 ccw(c121.966,23.93) 122.207,23.93 ccw(c122.448,23.93) v4@122.278,23.759 ; v4@122.207,23.713 U12-1.109@122.207,24.138 ; v4@122.636,23.759 ccw(c122.466,23.93) 122.707,23.93 ccw(c122.948,23.93) v4@122.778,23.759 ; v4@122.707,23.713 U12-1.107@122.707,24.138
  Bottom Layer w0.2: v4@122.136,23.617 cw(c121.966,23.447) 122.207,23.447 cw(c122.448,23.447) 122.278,23.617 cw(c122.448,23.447) 122.448,23.688 cw(c122.448,23.93) 122.278,23.759 cw(c122.448,23.93) 122.207,23.93 cw(c121.966,23.93) v4@122.136,23.759 ; L23-1.1@122.207,26.088 v4(122.207,23.688) ; C88-1.1@122.357,23.088 122.207,23.238 v4(122.207,23.688) ; v4@122.636,23.617 ccw(c122.466,23.447) 122.466,23.688 ccw(c122.466,23.93) v4@122.636,23.759 ; v4(122.707,23.688) v4(122.207,23.688)
NetC88-2_1: C88-2.1 L23-2.1 U12-2.107 U12-2.109 | length 5
  Top Layer w0.2: v4@122.175,73.051 ccw(c122.005,73.221) 122.246,73.221 ccw(c122.487,73.221) v4@122.317,73.051 ; v4@122.246,73.005 U12-2.109@122.246,73.43
  Top Layer w0.3: U12-2.109@122.321,73.43 U12-2.107@122.746,73.43
  Bottom Layer w0.2: v4@122.175,72.909 cw(c122.005,72.738) 122.246,72.738 cw(c122.487,72.738) v4@122.317,72.909 ; v4@122.175,73.051 ccw(c122.005,73.221) 122.246,73.221 ccw(c122.487,73.221) v4@122.317,73.051 ; L23-2.1@122.246,75.38 v4(122.246,72.98) 122.246,72.53 C88-2.1@122.396,72.38
NetC89-1_1: C89-1.1 L24-1.2 U12-1.59 U12-1.62 U12-1.63 | length 8.7
  Top Layer w0.15: U12-1.62@127.707,17.638 127.757,17.638 127.957,17.838 128.232,17.838 U12-1.63@128.282,17.888 ; U12-1.59@128.282,16.888 v1(128.857,16.888) ; v1@128.751,16.782 ccw(c128.495,16.526) 128.495,16.888 ccw(c128.495,17.25) v1@128.751,16.994
  Top Layer w0.2: v4@127.282,17.638 U12-1.62@127.707,17.638 ; v4@127.328,17.567 cw(c127.498,17.397) 127.498,17.638 cw(c127.498,17.879) v4@127.328,17.709
  Bottom Layer w0.15: C89-1.1@126.707,17.638 128.107,17.638 v1(128.857,16.888) L24-1.2@130.357,16.888 ; v4@127.169,17.55 ccw(c126.955,17.336) 126.955,17.638 ccw(c126.955,17.94) v4@127.169,17.726 ; v4@127.345,17.55 cw(c127.559,17.336) 127.559,17.638 cw(c127.559,17.94) v4@127.345,17.726 ; v1@128.707,16.888 ccw(c128.345,16.888) 128.601,17.144 ccw(c128.857,17.4) v1@128.857,17.038 ; v1@128.963,16.782 cw(c129.219,16.526) 129.219,16.888 cw(c129.219,17.25) v1@128.963,16.994
  other v4: 127.257,17.638
NetC89-2_1: C89-2.1 L24-2.2 U12-2.59 U12-2.62 U12-2.63 | length 8.7
  Top Layer w0.15: U12-2.62@127.746,66.93 127.796,66.93 127.996,67.13 128.271,67.13 U12-2.63@128.321,67.18 ; U12-2.59@128.321,66.18 v1(128.896,66.18) ; v1@128.79,66.074 ccw(c128.534,65.818) 128.534,66.18 ccw(c128.534,66.542) v1@128.79,66.286
  Top Layer w0.2: v4@127.321,66.93 U12-2.62@127.746,66.93 ; v4@127.367,66.859 cw(c127.537,66.688) 127.537,66.93 cw(c127.537,67.171) v4@127.367,67.001
  Bottom Layer w0.15: C89-2.1@126.746,66.93 128.146,66.93 v1(128.896,66.18) L24-2.2@130.396,66.18 ; v4@127.208,66.841 ccw(c126.994,66.628) 126.994,66.93 ccw(c126.994,67.232) v4@127.208,67.018 ; v4@127.384,66.841 cw(c127.598,66.628) 127.598,66.93 cw(c127.598,67.232) v4@127.384,67.018 ; v1@128.746,66.18 ccw(c128.384,66.18) 128.64,66.436 ccw(c128.896,66.692) v1@128.896,66.33 ; v1@129.002,66.074 cw(c129.258,65.818) 129.258,66.18 cw(c129.258,66.542) v1@129.002,66.286
  other v4: 127.296,66.93
NetC90-1_1: C90-1.1 L25-1.1 U12-1.90 U12-1.101 | length 8.8
  Top Layer w0.15: v1@126.851,25.182 cw(c126.595,24.926) 126.957,24.926 cw(c127.319,24.926) v1@127.063,25.182 ; v1@126.851,25.394 ccw(c126.595,25.65) 126.957,25.65 ccw(c127.319,25.65) v1@127.063,25.394 ; U12-1.90@126.957,24.713 v1(126.957,25.288) 126.957,25.838 127.757,25.838 L25-1.1@127.907,25.988
  Top Layer w0.2: v4@124.136,23.759 ccw(c123.966,23.93) 124.207,23.93 ccw(c124.448,23.93) v4@124.278,23.759 ; v4@124.207,23.713 U12-1.101@124.207,24.138
  Bottom Layer w0.15: v4(124.207,23.688) 124.207,23.718 124.627,24.138 126.257,24.138 126.957,24.838 v1(126.957,25.288) ; v4@124.207,23.813 ccw(c124.207,24.042) 124.369,23.88 ; v4@124.332,23.688 cw(c124.707,23.688) 124.442,23.953 ; v1@126.851,25.182 cw(c126.595,24.926) 126.957,24.926 cw(c127.319,24.926) v1@127.063,25.182
NetC90-2_1: C90-2.1 L25-2.1 U12-2.90 U12-2.101 | length 8.8
  Top Layer w0.15: v1@126.89,74.474 cw(c126.634,74.218) 126.996,74.218 cw(c127.358,74.218) v1@127.102,74.474 ; v1@126.89,74.686 ccw(c126.634,74.942) 126.996,74.942 ccw(c127.358,74.942) v1@127.102,74.686 ; U12-2.90@126.996,74.005 v1(126.996,74.58) 126.996,75.13 127.796,75.13 L25-2.1@127.946,75.28
  Top Layer w0.2: v4@124.175,73.051 ccw(c124.005,73.221) 124.246,73.221 ccw(c124.487,73.221) v4@124.317,73.051 ; v4@124.246,73.005 U12-2.101@124.246,73.43
  Bottom Layer w0.15: v4(124.246,72.98) 124.246,73.01 124.666,73.43 126.296,73.43 126.996,74.13 v1(126.996,74.58) ; v4@124.246,73.105 ccw(c124.246,73.333) 124.408,73.172 ; v4@124.371,72.98 cw(c124.746,72.98) 124.481,73.245 ; v1@126.89,74.474 cw(c126.634,74.218) 126.996,74.218 cw(c127.358,74.218) v1@127.102,74.474
NetC91-1_1: C91-1.1 L26-1.2 U12-1.78 U12-1.79 U12-1.81 U12-1.82 U12-1.85 | length 9.2
  Top Layer w0.2: U12-1.78@127.707,21.638 127.807,21.738 128.057,21.738 128.207,21.888 U12-1.79@128.282,21.888 128.657,21.888 128.807,22.038 128.807,22.388 ; U12-1.82@127.707,22.638 127.807,22.538 128.057,22.538 128.207,22.388 128.807,22.388 ; U12-1.85@128.282,23.388 v1@129.107,23.388 ; v1@129.119,22.3 ccw(c128.905,22.086) 128.905,22.388 ccw(c128.905,22.69) v1@129.119,22.476 ; v1@129.119,23.3 ccw(c128.905,23.086) 128.905,23.388 ccw(c128.905,23.69) v1@129.119,23.476 ; v1@129.295,22.3 cw(c129.509,22.086) 129.509,22.388 cw(c129.509,22.69) v1@129.295,22.476 ; L26-1.2@130.257,21.738 130.257,22.438 130.207,22.388 v1(129.207,22.388) 128.807,22.388
  Bottom Layer w0.2: v1@129.119,22.476 ccw(c128.905,22.69) 129.207,22.69 ccw(c129.509,22.69) v1@129.295,22.476 ; v1@129.119,23.3 cw(c128.905,23.086) 129.207,23.086 cw(c129.509,23.086) v1@129.295,23.3 ; v1(129.207,22.388) v1(129.207,23.388)
NetC91-2_1: C91-2.1 L26-2.2 U12-2.78 U12-2.79 U12-2.81 U12-2.82 U12-2.85 | length 9.2
  Top Layer w0.2: U12-2.78@127.746,70.93 127.846,71.03 128.096,71.03 128.246,71.18 U12-2.79@128.321,71.18 128.696,71.18 128.846,71.33 128.846,71.68 ; U12-2.82@127.746,71.93 127.846,71.83 128.096,71.83 128.246,71.68 128.846,71.68 ; U12-2.85@128.321,72.68 v1@129.146,72.68 ; v1@129.158,71.591 ccw(c128.944,71.378) 128.944,71.68 ccw(c128.944,71.982) v1@129.158,71.768 ; v1@129.158,72.591 ccw(c128.944,72.378) 128.944,72.68 ccw(c128.944,72.982) v1@129.158,72.768 ; v1@129.334,71.591 cw(c129.548,71.378) 129.548,71.68 cw(c129.548,71.982) v1@129.334,71.768 ; L26-2.2@130.296,71.03 130.296,71.73 130.246,71.68 v1(129.246,71.68) 128.846,71.68
  Bottom Layer w0.2: v1@129.158,71.768 ccw(c128.944,71.982) 129.246,71.982 ccw(c129.548,71.982) v1@129.334,71.768 ; v1@129.158,72.591 cw(c128.944,72.378) 129.246,72.378 cw(c129.548,72.378) v1@129.334,72.591 ; v1(129.246,71.68) v1(129.246,72.68)
NetC92-1_1: C92-1.1 L27-1.1 U12-1.43 U12-1.45 U12-1.47 U12-1.49 | length 10.9
  Top Layer w0.2: v4@123.636,17.017 cw(c123.466,16.847) 123.707,16.847 cw(c123.948,16.847) v4@123.778,17.017 ; U12-1.43@123.707,16.638 v4@123.707,17.063 ; v4@124.136,17.017 cw(c123.966,16.847) 124.207,16.847 cw(c124.448,16.847) v4@124.278,17.017 ; U12-1.45@124.207,16.638 v4@124.207,17.063 ; v4@124.636,17.017 cw(c124.466,16.847) 124.707,16.847 cw(c124.948,16.847) v4@124.778,17.017 ; U12-1.47@124.707,16.638 v4@124.707,17.063 ; v4@125.136,17.017 cw(c124.966,16.847) 125.207,16.847 cw(c125.448,16.847) v4@125.278,17.017 ; U12-1.49@125.207,16.638 v4@125.207,17.063
  Bottom Layer w0.2: v4(123.707,17.088) v4(124.207,17.088) v4(124.707,17.088) ; v4@123.778,17.017 cw(c123.948,16.847) 123.948,17.088 cw(c123.948,17.329) v4@123.778,17.159 ; v4@124.136,17.017 ccw(c123.966,16.847) 123.966,17.088 ccw(c123.966,17.329) v4@124.136,17.159 ; v4@124.278,17.017 cw(c124.448,16.847) 124.448,17.088 cw(c124.448,17.329) v4@124.278,17.159 ; C92-1.1@124.557,17.688 124.707,17.538 v4(124.707,17.088) ; L27-1.1@124.857,14.638 124.707,14.788 v4(124.707,17.088) ; v4@125.136,17.017 ccw(c124.966,16.847) 124.966,17.088 ccw(c124.966,17.329) v4@125.136,17.159 ; v4(125.207,17.088) v4(124.707,17.088) ; 124.466,17.088 ccw(c124.466,17.329) 124.636,17.159 ccw(c124.466,17.329) 124.707,17.329 ccw(c124.948,17.329) 124.778,17.159 ccw(c124.948,17.329) 124.948,17.088 ccw(c124.948,16.847) 124.778,17.017 ccw(c124.948,16.847) 124.707,16.847 ccw(c124.466,16.847) 124.636,17.017 ccw(c124.466,16.847) 124.466,17.088
NetC92-2_1: C92-2.1 L27-2.1 U12-2.43 U12-2.45 U12-2.47 U12-2.49 | length 6
  Top Layer w0.3: U12-2.43@123.746,65.93 U12-2.45@124.246,65.93 U12-2.47@124.746,65.93 ; v4@124.746,66.355 U12-2.47@124.746,65.93 ; U12-2.49@125.246,65.93 U12-2.47@124.746,65.93
  Bottom Layer w0.2: C92-2.1@124.596,66.98 124.746,66.83 v4(124.746,66.38) 125.1,66.026 125.1,64.134 L27-2.1@124.896,63.93 ; v4@124.675,66.451 ccw(c124.505,66.621) 124.746,66.621 ccw(c124.987,66.621) v4@124.817,66.451 ; v4@124.746,66.28 cw(c124.746,66.038) 124.917,66.209 cw(c125.087,66.38) v4@124.846,66.38
NetC93-1_1: C93-1.1 L28-1.2 U12-1.86 | length 5.1
  Top Layer w0.2: U12-1.86@127.707,23.638 127.707,24.289 129.668,26.25 130.257,26.25 130.257,27.088 L28-1.2@130.407,27.238
NetC93-2_1: C93-2.1 L28-2.2 U12-2.86 | length 5.1
  Top Layer w0.2: U12-2.86@127.746,72.93 127.746,73.581 129.595,75.43 C93-2.1@130.296,75.43 ; C93-2.1@130.296,75.48 130.296,76.38 L28-2.2@130.446,76.53
NetC94-1_2: C94-1.2 C95-1.1 L29-1.1 L30-1.1 L31-1.1 | length 7.5
  Top Layer w0.15: L31-1.1@126.507,13.188 C95-1.1@126.507,12.038 L29-1.1@127.607,12.038
  Top Layer w0.2: L30-1.1@122.757,13.138 122.857,13.038 122.857,12.429 ; C94-1.2@122.857,11.738 122.857,12.429 ; C95-1.1@126.507,12.038 126.138,12.407 122.879,12.407 122.857,12.429
NetC94-2_2: C94-2.2 C95-2.1 L29-2.1 L30-2.1 L31-2.1 | length 7.5
  Top Layer w0.15: L31-2.1@126.546,62.48 C95-2.1@126.546,61.33 L29-2.1@127.646,61.33
  Top Layer w0.2: L30-2.1@122.796,62.43 122.896,62.33 122.896,61.721 ; C94-2.2@122.896,61.03 122.896,61.721 ; C95-2.1@126.546,61.33 126.177,61.699 122.918,61.699 122.896,61.721
NetC96-1_1: C96-1.1 C105-1.1 L31-1.2 U12-1.46 | length 4.4
  Top Layer w0.2: U12-1.46@124.457,16.063 124.457,15.638 C96-1.1@125.407,14.688 ; C105-1.1@125.357,13.138 125.407,13.188 C96-1.1@125.407,14.688 ; L31-1.2@126.507,14.688 C96-1.1@125.407,14.688
NetC96-1_2: C96-1.2 C104-1.1 L30-1.2 U12-1.44 | length 4.3
  Top Layer w0.2: L30-1.2@122.757,14.638 123.857,14.638 C96-1.2@123.907,14.688 ; C104-1.1@123.857,13.138 124.136,13.417 124.136,15.634 123.957,15.813 U12-1.44@123.957,16.063
NetC96-2_1: C96-2.1 C105-2.1 L31-2.2 U12-2.46 | length 4.4
  Top Layer w0.2: U12-2.46@124.496,65.355 124.496,64.93 C96-2.1@125.446,63.98 ; C105-2.1@125.396,62.43 125.446,62.48 C96-2.1@125.446,63.98 ; L31-2.2@126.546,63.98 C96-2.1@125.446,63.98
NetC96-2_2: C96-2.2 C104-2.1 L30-2.2 U12-2.44 | length 4.3
  Top Layer w0.2: L30-2.2@122.796,63.93 123.896,63.93 C96-2.2@123.946,63.98 ; C104-2.1@123.896,62.43 124.175,62.709 124.175,64.926 123.996,65.105 U12-2.44@123.996,65.355
NetC97-1_2: C97-1.2 R119-1.1 U12-1.87 | length 8
  Top Layer w0.15: U12-1.87@128.282,23.888 128.807,23.888 130.327,25.408 C97-1.2@130.411,25.408 130.911,24.908 ; C97-1.2@130.478,25.341 ccw(c131.161,26.023) v1@131.161,25.058 ; C97-1.2@130.734,25.085 ccw(c131.161,25.511) v1(131.161,24.908) 130.911,24.908 ; v1@131.029,24.838 ccw(c130.911,24.775) 130.911,24.908 ; v1@131.029,24.979 cw(c130.911,25.041) 130.911,24.908
  Bottom Layer w0.15: v1@131.055,24.802 cw(c130.799,24.546) 131.161,24.546 cw(c131.523,24.546) v1@131.267,24.802 ; v1(131.161,24.908) 131.111,24.858 131.161,24.808 131.161,23.708 131.411,23.458 131.711,23.458 R119-1.1@131.911,23.258
NetC97-2_2: C97-2.2 R119-2.1 U12-2.87 | length 8
  Top Layer w0.15: U12-2.87@128.321,73.18 128.846,73.18 130.366,74.7 130.45,74.7 130.95,74.2 ; C97-2.2@130.517,74.633 ccw(c131.2,75.315) v1@131.2,74.35 ; C97-2.2@130.773,74.377 ccw(c131.2,74.803) v1(131.2,74.2) 130.95,74.2 ; v1@131.067,74.129 ccw(c130.95,74.067) 130.95,74.2 ; v1@131.068,74.271 cw(c130.95,74.333) 130.95,74.2
  Bottom Layer w0.15: v1@131.094,74.094 cw(c130.838,73.838) 131.2,73.838 cw(c131.562,73.838) v1@131.306,74.094 ; v1(131.2,74.2) 131.15,74.15 131.2,74.1 131.2,73 131.45,72.75 131.75,72.75 R119-2.1@131.95,72.55
NetC98-1_1: C98-1.1 C99-1.1 R119-1.2 U12-1.80 | length 7.5
  Top Layer w0.2: v4@127.282,22.138 U12-1.80@127.707,22.138 ; v4@127.328,22.067 cw(c127.498,21.897) 127.498,22.138 cw(c127.498,22.379) v4@127.328,22.209
  Bottom Layer w0.2: v4(127.257,22.138) 129.527,24.408 C98-1.1@130.411,24.408 ; v4@127.257,22.238 ccw(c127.257,22.479) 127.428,22.309 ccw(c127.598,22.138) v4@127.357,22.138 ; R119-1.2@130.411,23.258 C98-1.1@130.411,24.408 ; C99-1.1@130.411,25.508 C98-1.1@130.411,24.408
NetC98-2_1: C98-2.1 C99-2.1 R119-2.2 U12-2.80 | length 7.5
  Top Layer w0.2: v4@127.321,71.43 U12-2.80@127.746,71.43 ; v4@127.367,71.359 cw(c127.537,71.188) 127.537,71.43 cw(c127.537,71.671) v4@127.367,71.501
  Bottom Layer w0.2: v4(127.296,71.43) 129.566,73.7 C98-2.1@130.45,73.7 ; v4@127.296,71.53 ccw(c127.296,71.771) 127.467,71.601 ccw(c127.637,71.43) v4@127.396,71.43 ; R119-2.2@130.45,72.55 C98-2.1@130.45,73.7 ; C99-2.1@130.45,74.8 C98-2.1@130.45,73.7
NetC99-1_2: C99-1.2 R121-1.1 | length 1.7
  Bottom Layer w0.2: C99-1.2@131.911,25.508 132.161,25.758 R121-1.1@133.461,25.758
NetC99-2_2: C99-2.2 R121-2.1 | length 1.7
  Bottom Layer w0.2: C99-2.2@131.95,74.8 132.2,75.05 R121-2.1@133.5,75.05
NetC100-1_1: C100-1.1 C108-1.1 R126-1.1 U13-1.3 U13-1.7 U14-1.3 U14-1.7 | length 23.7
  Top Layer w0.3: R126-1.1@116.061,38.558 117.211,38.558 117.211,36.284 U13-1.3@117.176,36.249 117.176,33.843 v1(118.446,32.573) U13-1.7@118.446,30.661 ; C108-1.1@122.711,38.508 C108-1.1@122.711,38.458 122.711,36.314 U14-1.3@122.726,36.299 122.726,33.893 123.996,32.623 U14-1.7@123.996,30.711
  Bottom Layer w0.3: v1(118.446,32.573) 123.976,32.573 v1(124.011,32.608) ; 123.745,32.573 ccw(c123.745,32.874) v1@123.958,32.661
NetC100-2_1: C100-2.1 C108-2.1 R126-2.1 U13-2.3 U13-2.7 U14-2.3 U14-2.7 | length 23.7
  Top Layer w0.3: R126-2.1@116.1,87.85 117.25,87.85 117.25,85.576 U13-2.3@117.215,85.541 117.215,83.135 v1(118.485,81.865) U13-2.7@118.485,79.953 ; C108-2.1@122.75,87.8 C108-2.1@122.75,87.75 122.75,85.606 U14-2.3@122.765,85.591 122.765,83.185 124.035,81.915 U14-2.7@124.035,80.003
  Bottom Layer w0.3: v1(118.485,81.865) 124.015,81.865 v1(124.05,81.9) ; 123.784,81.865 ccw(c123.784,82.166) v1@123.997,81.953
NetC101-1_1: C101-1.1 C109-1.1 R127-1.1 U13-1.2 U14-1.2 | length 17.9
  Top Layer w0.2: v2@118.34,37.644 cw(c118.084,37.388) 118.446,37.388 cw(c118.808,37.388) v2@118.552,37.644 ; v2@118.34,37.856 ccw(c118.084,38.112) 118.446,38.112 ccw(c118.808,38.112) v2@118.552,37.856 ; U13-1.2@118.446,36.249 v2(118.446,37.75) 118.446,38.443 C101-1.1@118.511,38.508 ; U14-1.2@123.996,36.299 123.996,38.423 C109-1.1@123.961,38.458 R127-1.1@125.411,38.458 126.308,38.458 v2(126.35,38.5) ; 125.887,38.458 ccw(c125.887,38.963) v2@126.244,38.606 ; 126.089,38.458 cw(c126.089,38.239) v2@126.244,38.394
  Bottom Layer w0.2: v2(118.446,37.75) 119.196,38.5 v2(126.35,38.5) ; v2@118.446,37.9 ccw(c118.446,38.262) 118.702,38.006 ccw(c118.958,37.75) v2@118.596,37.75 ; v2@126.244,38.394 ccw(c125.988,38.138) 125.988,38.5 ccw(c125.988,38.862) v2@126.244,38.606
NetC101-2_1: C101-2.1 C109-2.1 R127-2.1 U13-2.2 U14-2.2 | length 17.5
  Top Layer w0.2: v1@118.412,86.912 cw(c118.234,86.734) 118.485,86.734 ; v1@118.412,87.088 ccw(c118.234,87.266) 118.485,87.266 ; U13-2.2@118.485,85.541 118.485,87.735 C101-2.1@118.55,87.8 ; 118.485,86.662 cw(c118.838,86.662) v1@118.588,86.912 ; 118.485,87.338 ccw(c118.838,87.338) v1@118.588,87.088 ; U14-2.2@124.035,85.591 124.035,87.715 C109-2.1@124,87.75 R127-2.1@125.45,87.75 v1(126.45,87.75) ; v1@126.362,87.662 ccw(c126.148,87.448) 126.148,87.75 ccw(c126.148,88.052) v1@126.362,87.838
  Bottom Layer w0.2: v1(118.5,87) 119.25,87.75 v1(126.45,87.75) ; v1@118.5,87.125 ccw(c118.5,87.427) 118.713,87.213 ccw(c118.927,87) v1@118.625,87 ; v1@126.362,87.662 ccw(c126.148,87.448) 126.148,87.75 ccw(c126.148,88.052) v1@126.362,87.838
NetC102-1_1: C102-1.1 U12-1.108 | length 1.9
  Top Layer w0.15: U12-1.108@122.457,24.713 122.457,25.104 123.011,25.658 C102-1.1@123.011,26.358
NetC102-1_2: C102-1.2 L32-1.1 | length 8.5
  Top Layer w0.15: C102-1.2@123.011,27.858 123.011,27.958 123.611,28.558 124.861,28.558 125.061,28.758 126.161,28.758 126.961,29.558 L32-1.1@126.961,32.758
  Top Layer w0.2: C102-1.2@123.011,27.858 C102-1.2@123.261,28.108 ; L32-1.1@126.661,32.658 L32-1.1@126.811,32.508
NetC102-2_1: C102-2.1 U12-2.108 | length 1.9
  Top Layer w0.15: U12-2.108@122.496,74.005 122.496,74.396 123.05,74.95 C102-2.1@123.05,75.65
NetC102-2_2: C102-2.2 L32-2.1 | length 8.5
  Top Layer w0.15: C102-2.2@123.05,77.15 123.05,77.25 123.65,77.85 124.9,77.85 125.1,78.05 126.2,78.05 127,78.85 L32-2.1@127,82.05
  Top Layer w0.2: C102-2.2@123.05,77.15 C102-2.2@123.3,77.4 ; L32-2.1@126.7,81.95 L32-2.1@126.85,81.8
NetC103-1_1: C103-1.1 U12-1.110 | length 1.6
  Top Layer w0.15: U12-1.110@121.957,24.713 121.957,26.354 C103-1.1@121.961,26.358
NetC103-1_2: C103-1.2 L33-1.1 | length 11.8
  Top Layer w0.15: C103-1.2@121.961,27.858 121.961,27.958 122.561,28.558 123.111,28.558 123.361,28.808 124.661,28.808 124.861,29.008 125.761,29.008 126.261,29.508 126.261,35.358 126.361,35.458 L33-1.1@126.961,35.458
  Top Layer w0.2: C103-1.2@121.961,27.858 C103-1.2@122.107,28.004
NetC103-2_1: C103-2.1 U12-2.110 | length 1.6
  Top Layer w0.15: U12-2.110@121.996,74.005 121.996,75.646 C103-2.1@122,75.65
NetC103-2_2: C103-2.2 L33-2.1 | length 11.8
  Top Layer w0.15: C103-2.2@122,77.15 122,77.25 122.6,77.85 123.15,77.85 123.4,78.1 124.7,78.1 124.9,78.3 125.8,78.3 126.3,78.8 126.3,84.65 126.4,84.75 L33-2.1@127,84.75
  Top Layer w0.2: C103-2.2@122,77.15 C103-2.2@122.146,77.296
NetC104-1_2: C104-1.2 T1-1.3 | length 6.3
  Top Layer w0.2: C104-1.2@123.857,11.638 123.857,10.148 124.361,9.644 124.361,6.908 124.511,6.758 125.631,6.758 T1-1.3@125.661,6.788
NetC104-2_2: C104-2.2 T1-2.3 | length 6.3
  Top Layer w0.2: C104-2.2@123.896,60.93 123.896,59.439 124.4,58.935 124.4,56.2 124.55,56.05 125.67,56.05 T1-2.3@125.7,56.08
NetC105-1_2: C105-1.2 T1-1.1 | length 2.4
  Top Layer w0.2: C105-1.2@125.357,11.638 125.357,10.212 ; 125.361,10.208 125.357,10.212 ; T1-1.1@125.661,9.328 125.357,9.632 125.357,10.212
NetC105-2_2: C105-2.2 T1-2.1 | length 2.4
  Top Layer w0.2: C105-2.2@125.396,60.93 125.396,59.504 ; 125.4,59.5 125.396,59.504 ; T1-2.1@125.7,58.62 125.396,58.924 125.396,59.504
NetC106-1_1: C106-1.1 U12-1.96 | length 1.6
  Top Layer w0.15: U12-1.96@125.457,24.713 125.457,25.054 125.911,25.508 C106-1.1@125.911,26.108
NetC106-1_2: C106-1.2 T2-1.1 | length 3.7
  Top Layer w0.2: C106-1.2@126.157,27.838 ccw(c126.157,28.041) 126.3,27.897 126.461,28.058 126.861,28.058 127.661,28.858 128.311,28.858 128.561,29.108 T2-1.1@128.561,29.838
NetC106-2_1: C106-2.1 U12-2.96 | length 1.6
  Top Layer w0.15: U12-2.96@125.496,74.005 125.496,74.346 125.95,74.8 C106-2.1@125.95,75.4
NetC106-2_2: C106-2.2 T2-2.1 | length 3.7
  Top Layer w0.2: C106-2.2@126.196,77.13 ccw(c126.196,77.332) 126.339,77.189 126.5,77.35 126.9,77.35 127.7,78.15 128.35,78.15 128.6,78.4 T2-2.1@128.6,79.13
NetC107-1_1: C107-1.1 U12-1.98 | length 1.7
  Top Layer w0.15: U12-1.98@124.957,24.713 124.957,26.204 C107-1.1@125.111,26.358
NetC107-1_2: C107-1.2 T2-1.3 | length 7.2
  Top Layer w0.15: C107-1.2@125.111,27.858 125.211,27.958 125.211,28.412 125.307,28.508 126.711,28.508 127.411,29.208 127.411,32.008 127.661,32.258 128.441,32.258 T2-1.3@128.561,32.378
NetC107-2_1: C107-2.1 U12-2.98 | length 1.7
  Top Layer w0.15: U12-2.98@124.996,74.005 124.996,75.496 C107-2.1@125.15,75.65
